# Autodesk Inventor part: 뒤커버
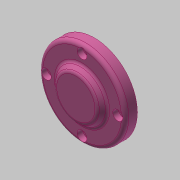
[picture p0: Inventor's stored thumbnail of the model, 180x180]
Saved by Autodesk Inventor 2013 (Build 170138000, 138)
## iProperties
Created: 2017-08
Part Number: 뒤커버
Material: 알루미늄 6061
Document SubType Name: Modeling
Designer: mduedu
Density: 1 g/cm^3
Author: mduedu
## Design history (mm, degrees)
sketch "스케치1"
  geometry: C1 r 35 at (0, 0); 1 further point
  constraints: 1 centre point, 1 coincident
  dimensions: "d0" = 70 diameter of C1
extrude "돌출1" new body sketch "스케치1" distance "d1" = 10; taper "d2" = 0 deg
sketch "스케치2"
  geometry: C1 r 21 at (0, 0); 1 further point
  constraints: 1 centre point, 1 coincident
  dimensions: "d3" = 42 diameter of C1
node "작업 평면1"
sketch "스케치3"
  geometry: C1 r 17 at (0, 0); 1 further point
  constraints: 1 centre point, 1 coincident
  dimensions: "d5" = 34 diameter of C1
feature "로프트1" sketch "스케치3" dims "d6" = 0, "d7" = 90 deg, "d8" = 0, "d9" = 90 deg
sketch "스케치4"
  geometry: C1 r 24 at (0, 0); 1 further point
  constraints: 1 centre point, 1 coincident
  dimensions: "d65" = 48 diameter of C1
extrude "돌출2" join sketch "스케치4" distance "d10" = 8; taper "d11" = 0 deg
hole "구멍1" diameter "d14" = 40; stored, may be unused: countersink angle "d18" = 90 deg, drill point angle "d20" = 0 deg; dims "d15" = 6, "d16" = 4, "d17" = 2, "d19" = 12, "d66" = 10, "d67" = 10
hole "구멍2" diameter "d23" = 34; stored, may be unused: countersink angle "d27" = 90 deg, drill point angle "d29" = 0 deg; dims "d24" = 6, "d25" = 4, "d26" = 2, "d28" = 6, "d62" = 10, "d63" = 10
chamfer "모따기1" distance "d39" = 1; stored, may be unused: second distance "d40" = 2, angle "d41" = 45 deg
fillet "모깎기1" dims "d42" = 0.3
fillet "모깎기2" dims "d43" = 3
sketch "스케치5" dims "d44" = 58
  geometry: 6 further points
  constraints: 2 vertical alignment, 1 coincident, 7 other
  dimensions: "d47" = 360 deg dimension on point (0, 0) point (0, 29) (derived)
sketch "스케치6" dims "d64" = 58 (derived)
  geometry: 6 further points
  constraints: 1 coincident, 1 vertical alignment, 6 other
hole "구멍4" sketch "스케치6" at (0, 29), (-29, 0), (29, 0), (0, -29) diameter "d49" = 4.5; stored, may be unused: countersink angle "d53" = 90 deg, drill point angle "d55" = 0 deg; dims "d50" = 6, "d51" = 8, "d52" = 4.6, "d54" = 8
fillet "모깎기3" dims "d56" = 3
fillet "모깎기4" dims "d57" = 3
fillet "모깎기5" dims "d58" = 3
node "솔리드1"
other parameters: "d4" = 5
